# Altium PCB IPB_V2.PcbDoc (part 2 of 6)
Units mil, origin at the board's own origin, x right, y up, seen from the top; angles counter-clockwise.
Board outline 14000 x 12000 mil, 6 copper layers (Top, L2 - Plane/Horiz, L3 - Horiz, L4 - Vert, L5 - Plane/Horiz, Bottom), stack 61.468 mil thick; 657 components, 436 nets, 1897 pads, 873 vias.
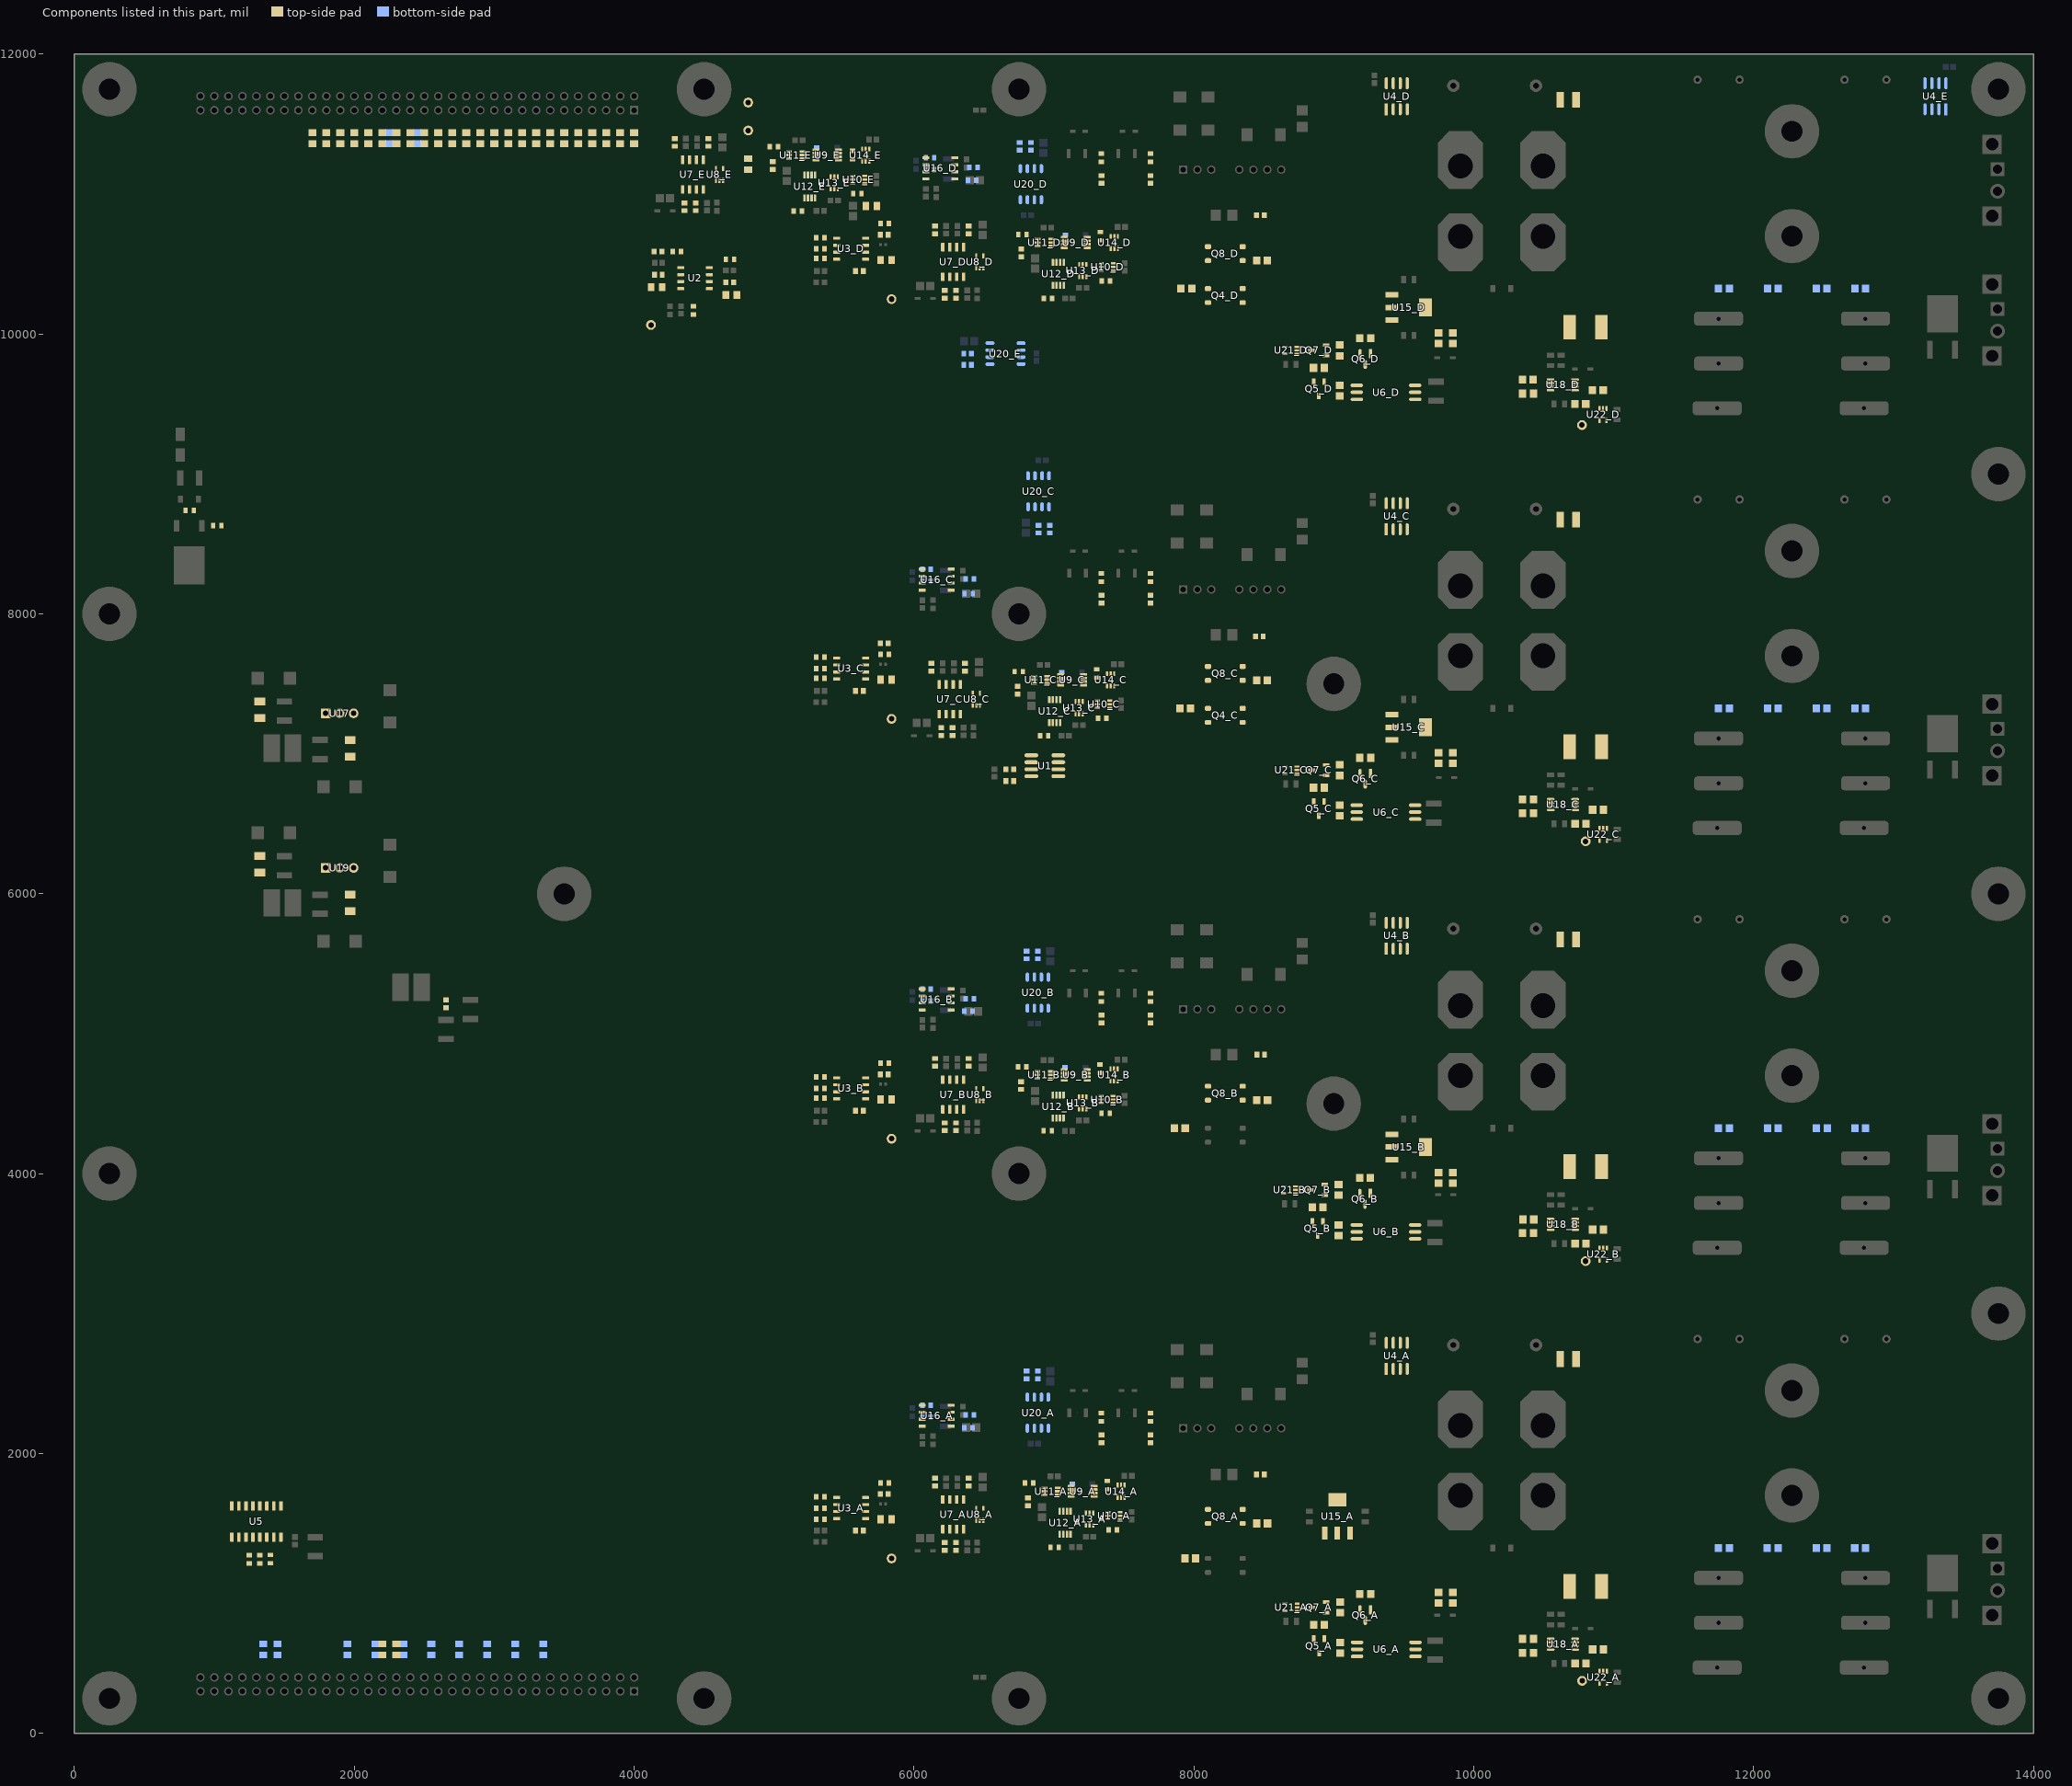
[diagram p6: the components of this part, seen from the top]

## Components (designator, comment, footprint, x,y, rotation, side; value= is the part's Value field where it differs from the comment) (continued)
Q4_C "140357145100" WL-OCPT_SOP4 8225,7275 r0 top (schematic designator Q4)
Q4_D "140357145100" WL-OCPT_SOP4 8225,10275 r0 top (schematic designator Q4)
Q5_A "MMBT3906LT1G" SOT95P237X111-3M 8895,625 r270 top (schematic designator Q5)
Q5_B "MMBT3906LT1G" SOT95P237X111-3M 8884.76,3608.66 r270 top (schematic designator Q5)
Q5_C "MMBT3906LT1G" SOT95P237X111-3M 8893.42,6608.66 r270 top (schematic designator Q5)
Q5_D "MMBT3906LT1G" SOT95P237X111-3M 8893.42,9608.66 r270 top (schematic designator Q5)
Q6_A "BSS138P,215" FP-SOT23-IPC_A 9225,845 r270 top (schematic designator Q6)
Q6_B "BSS138P,215" FP-SOT23-IPC_A 9223.42,3820 r270 top (schematic designator Q6)
Q6_C "BSS138P,215" FP-SOT23-IPC_A 9225,6821.58 r270 top (schematic designator Q6)
Q6_D "BSS138P,215" FP-SOT23-IPC_A 9225,9821.58 r270 top (schematic designator Q6)
Q7_A "MMBT3904LT1G" SOT95P237X111-3M 8895,900 r180 top (schematic designator Q7)
Q7_B "MMBT3904LT1G" SOT95P237X111-3M 8884.76,3883.66 r180 top (schematic designator Q7)
Q7_C "MMBT3904LT1G" SOT95P237X111-3M 8893.42,6883.66 r180 top (schematic designator Q7)
Q7_D "MMBT3904LT1G" SOT95P237X111-3M 8893.42,9883.66 r180 top (schematic designator Q7)
Q8_A "140357145100" WL-OCPT_SOP4 8225,1550 r180 top (schematic designator Q8)
Q8_B "140357145100" WL-OCPT_SOP4 8225,4575 r180 top (schematic designator Q8)
Q8_C "140357145100" WL-OCPT_SOP4 8225,7575 r180 top (schematic designator Q8)
Q8_D "140357145100" WL-OCPT_SOP4 8225,10575 r180 top (schematic designator Q8)
R1 "Resistor 51R1 +/-1% 0603 100 mW" RESC1609X50X30ML08T20 6685,6805 r0 top value=51.1
R2 "Resistor 7K15 +/-1% 0603 100 mW" RESC1609X50X30ML08T20 6685,6890 r0 top value=7.15k
R3 "Resistor 0R +/- 5% 0805 125 mW" RESC2013X60X35ML10T20 3200,11400 r90 top value=0
R4 "Resistor 0R +/- 5% 0805 125 mW" RESC2013X60X35ML10T20 4000,11400 r90 top value=0
R5 "Resistor 0R +/- 5% 0805 125 mW" RESC2013X60X35ML10T20 3100,11400 r90 top value=0
R6 "Resistor 0R +/- 5% 0805 125 mW" RESC2013X60X35ML10T20 3900,11400 r90 top value=0
R7 "Resistor 0R +/- 5% 0805 125 mW" RESC2013X60X35ML10T20 2800,11400 r90 top value=0
R8 "Resistor 0R +/- 5% 0805 125 mW" RESC2013X60X35ML10T20 3800,11400 r90 top value=0
R9 "Resistor 0R +/- 5% 0805 125 mW" RESC2013X60X35ML10T20 2700,11400 r90 top value=0
R10 "Resistor 0R +/- 5% 0805 125 mW" RESC2013X60X35ML10T20 3700,11400 r90 top value=0
R11 "Resistor 0R +/- 5% 0805 125 mW" RESC2013X60X35ML10T20 2400,11400 r90 top value=0
R12 "Resistor 0R +/- 5% 0805 125 mW" RESC2013X60X35ML10T20 3600,11400 r90 top value=0
R13 "Resistor 0R +/- 5% 0805 125 mW" RESC2013X60X35ML10T20 2300,11400 r90 top value=0
R14 "Resistor 0R +/- 5% 0805 125 mW" RESC2013X60X35ML10T20 3500,11400 r90 top value=0
R15 "Resistor 0R +/- 5% 0805 125 mW" RESC2013X60X35ML10T20 2000,11400 r90 top value=0
R16 "Resistor 0R +/- 5% 0805 125 mW" RESC2013X60X35ML10T20 3400,11400 r90 top value=0
R17 "Resistor 0R +/- 5% 0805 125 mW" RESC2013X60X35ML10T20 1900,11400 r90 top value=0
R18 "Resistor 0R +/- 5% 0805 125 mW" RESC2013X60X35ML10T20 3300,11400 r90 top value=0
R19 "Resistor 0R +/- 5% 0805 125 mW" RESC2013X60X35ML10T20 3000,11400 r90 top value=0
R20 "Resistor 0R +/- 5% 0805 125 mW" RESC2013X60X35ML10T20 3350,599.37 r270 bottom value=0
R21 "Resistor 0R +/- 5% 0805 125 mW" RESC2013X60X35ML10T20 2900,11400 r90 top value=0
R22 "Resistor 0R +/- 5% 0805 125 mW" RESC2013X60X35ML10T20 3150,599.37 r270 bottom value=0
R23 "Resistor 0R +/- 5% 0805 125 mW" RESC2013X60X35ML10T20 2600,11400 r90 top value=0
R24 "Resistor 0R +/- 5% 0805 125 mW" RESC2013X60X35ML10T20 2950,599.37 r270 bottom value=0
R25 "Resistor 0R +/- 5% 0805 125 mW" RESC2013X60X35ML10T20 2500,11400 r90 top value=0
R26 "Resistor 0R +/- 5% 0805 125 mW" RESC2013X60X35ML10T20 2750,599.37 r270 bottom value=0
R27 "Resistor 0R +/- 5% 0805 125 mW" RESC2013X60X35ML10T20 2200,11400 r90 top value=0
R28 "Resistor 0R +/- 5% 0805 125 mW" RESC2013X60X35ML10T20 2550,599.37 r270 bottom value=0
R29 "Resistor 0R +/- 5% 0805 125 mW" RESC2013X60X35ML10T20 2100,11400 r90 top value=0
R30 "Resistor 0R +/- 5% 0805 125 mW" RESC2013X60X35ML10T20 2350,599.37 r270 bottom value=0
R31 "Resistor 0R +/- 5% 0805 125 mW" RESC2013X60X35ML10T20 1800,11400 r90 top value=0
R32 "Resistor 0R +/- 5% 0805 125 mW" RESC2013X60X35ML10T20 2150,599.37 r270 bottom value=0
R33 "Resistor 0R +/- 5% 0805 125 mW" RESC2013X60X35ML10T20 2450,11400 r90 bottom value=0
R34 "Resistor 0R +/- 5% 0805 125 mW" RESC2013X60X35ML10T20 1700,11400 r90 top value=0
R35 "Resistor 0R +/- 5% 0805 125 mW" RESC2013X60X35ML10T20 1950,599.37 r270 bottom value=0
R36 "Resistor 0R +/- 5% 0805 125 mW" RESC2013X60X35ML10T20 2250,11400 r90 bottom value=0
R37 "Resistor 0R +/- 5% 0805 125 mW" RESC2013X60X35ML10T20 2300,600 r270 top value=0
R38 "Resistor 0R +/- 5% 0805 125 mW" RESC2013X60X35ML10T20 2200,600 r270 top value=0
R39 "Resistor 0R +/- 5% 0805 125 mW" RESC2013X60X35ML10T20 1450,599.37 r270 bottom value=0
R40 "Resistor 0R +/- 5% 0805 125 mW" RESC2013X60X35ML10T20 1350,599.37 r270 bottom value=0
R41 "Resistor 0R +/- 5% 0805 125 mW" RESC2013X60X35ML10T20 4815,11214.84 r270 top value=0
R42 "Resistor 0R +/- 5% 0805 125 mW" RESC2013X60X35ML10T20 5695,10915 r0 top value=0
R43 "Resistor 8K25 +/-1% 0603 100 mW" RESC1609X50X30ML08T20 4683.19,10370 r0 top value=8.25k
R44 "Resistor 10k +/-1% 0603 100 mW" RESC1608X55X25ML10T15 4425,10170 r90 top value=10k
R45 "Resistor 0R +/- 5% 0805 125 mW" RESC2013X60X35ML10T20 4695,10280 r180 top value=0
R46 "Resistor 45K3 +/-1% 0603 100 mW" RESC1608X55X25ML10T15 4685.16,10535 r180 top value=45.3k
R47 "Resistor 2K49 +/-1% 0603 100 mW" RESC1609X50X30ML08T20 4172.56,10425 r180 top value=2.49k
R48 "Resistor 3K32 +/-1% 0603 100 mW" RESC1609X50X30ML08T20 4170.47,10590 r0 top value=3.32k
R49 "Resistor 0R +/- 5% 0805 125 mW" RESC2013X60X35ML10T20 4160.75,10335 r0 top value=0
R50 "Resistor 10k +/-1% 0603 100 mW" RESC1608X55X25ML10T15 4305,10590 r180 top value=10k
R51_A "Resistor 4K53 +/-1% 0603 100 mW" RESC1609X50X30ML08T20 5610,1450 r0 top value=4.53k (schematic designator R51)
R51_B "Resistor 4K53 +/-1% 0603 100 mW" RESC1609X50X30ML08T20 5610,4450 r0 top value=4.53k (schematic designator R51)
R51_C "Resistor 4K53 +/-1% 0603 100 mW" RESC1609X50X30ML08T20 5610,7450 r0 top value=4.53k (schematic designator R51)
R51_D "Resistor 4K53 +/-1% 0603 100 mW" RESC1609X50X30ML08T20 5610,10450 r0 top value=4.53k (schematic designator R51)
R52_A "Resistor 10k +/-1% 0603 100 mW" RESC1608X55X25ML10T15 5790.16,1790 r0 top value=10k (schematic designator R52)
R52_B "Resistor 10k +/-1% 0603 100 mW" RESC1608X55X25ML10T15 5790.16,4790 r0 top value=10k (schematic designator R52)
R52_C "Resistor 10k +/-1% 0603 100 mW" RESC1608X55X25ML10T15 5790.16,7710 r0 top value=10k (schematic designator R52)
R52_D "Resistor 10k +/-1% 0603 100 mW" RESC1608X55X25ML10T15 5790.16,10790 r0 top value=10k (schematic designator R52)
R53_A "Resistor 0R +/- 5% 0805 125 mW" RESC2013X60X35ML10T20 5800,1530 r180 top value=0 (schematic designator R53)
R53_B "Resistor 0R +/- 5% 0805 125 mW" RESC2013X60X35ML10T20 5800,4530 r180 top value=0 (schematic designator R53)
R53_C "Resistor 0R +/- 5% 0805 125 mW" RESC2013X60X35ML10T20 5800,7530 r180 top value=0 (schematic designator R53)
R53_D "Resistor 0R +/- 5% 0805 125 mW" RESC2013X60X35ML10T20 5800,10530 r180 top value=0 (schematic designator R53)
R54_A "Resistor 8K45 +/-1% 0603 100 mW" RESC1609X50X30ML08T20 5788.19,1710 r180 top value=8.45k (schematic designator R54)
R54_B "Resistor 8K45 +/-1% 0603 100 mW" RESC1609X50X30ML08T20 5788.19,4710 r180 top value=8.45k (schematic designator R54)
R54_C "Resistor 8K45 +/-1% 0603 100 mW" RESC1609X50X30ML08T20 5788.19,7790 r180 top value=8.45k (schematic designator R54)
R54_D "Resistor 8K45 +/-1% 0603 100 mW" RESC1609X50X30ML08T20 5788.19,10710 r180 top value=8.45k (schematic designator R54)
R55_A "Resistor 10k +/-1% 0603 100 mW" RESC1608X55X25ML10T15 5330,1610 r180 top value=10k (schematic designator R55)
R55_B "Resistor 10k +/-1% 0603 100 mW" RESC1608X55X25ML10T15 5330,4610 r180 top value=10k (schematic designator R55)
R55_C "Resistor 10k +/-1% 0603 100 mW" RESC1608X55X25ML10T15 5330,7610 r180 top value=10k (schematic designator R55)
R55_D "Resistor 10k +/-1% 0603 100 mW" RESC1608X55X25ML10T15 5330,10610 r180 top value=10k (schematic designator R55)
R56_A "Resistor 10k +/-1% 0603 100 mW" RESC1608X55X25ML10T15 5330,1690 r0 top value=10k (schematic designator R56)
R56_B "Resistor 10k +/-1% 0603 100 mW" RESC1608X55X25ML10T15 5330,4690 r0 top value=10k (schematic designator R56)
R56_C "Resistor 10k +/-1% 0603 100 mW" RESC1608X55X25ML10T15 5330,7690 r0 top value=10k (schematic designator R56)
R56_D "Resistor 10k +/-1% 0603 100 mW" RESC1608X55X25ML10T15 5330,10690 r0 top value=10k (schematic designator R56)
R57_A "Resistor 10k +/-1% 0603 100 mW" RESC1608X55X25ML10T15 5330,1530 r0 top value=10k (schematic designator R57)
R57_B "Resistor 10k +/-1% 0603 100 mW" RESC1608X55X25ML10T15 5330,4540 r0 top value=10k (schematic designator R57)
R57_C "Resistor 10k +/-1% 0603 100 mW" RESC1608X55X25ML10T15 5330,7540 r0 top value=10k (schematic designator R57)
R57_D "Resistor 10k +/-1% 0603 100 mW" RESC1608X55X25ML10T15 5330,10540 r0 top value=10k (schematic designator R57)
R58 "Resistor 49K9 +/-1% 0603 100 mW" RESC1608X55X25ML10T15 822.8,8740 r180 top value=49.9k
R59 "Resistor 3R9 +/-1% 0603 100 mW" RESC1609X50X30ML08T20 2655,5213.78 r90 top value=3.9
R60 "Resistor 49K9 +/-1% 0603 100 mW" RESC1608X55X25ML10T15 1020,8630 r180 top value=49.9k
R61_A "Resistor 2K80 +/-1% 0603 100 mW" RESC1609X50X30ML08T20 8475,1850 r180 top value=2.8k (schematic designator R61)
R61_B "Resistor 2K80 +/-1% 0603 100 mW" RESC1609X50X30ML08T20 8477.56,4850 r180 top value=2.8k (schematic designator R61)
R61_C "Resistor 2K80 +/-1% 0603 100 mW" RESC1609X50X30ML08T20 8467.56,7840 r180 top value=2.8k (schematic designator R61)
R61_D "Resistor 2K80 +/-1% 0603 100 mW" RESC1609X50X30ML08T20 8475,10850 r180 top value=2.8k (schematic designator R61)
R62_A "RES 0805 4K99 1%" PANASONIC_ERJ6E 10763.39,500 r0 top value=4.99k (schematic designator R62)
R62_B "RES 0805 4K99 1%" PANASONIC_ERJ6E 10763.39,3500.2 r0 top value=4.99k (schematic designator R62)
R62_C "RES 0805 4K99 1%" PANASONIC_ERJ6E 10763.39,6500.2 r0 top value=4.99k (schematic designator R62)
R62_D "RES 0805 4K99 1%" PANASONIC_ERJ6E 10762.36,9500 r0 top value=4.99k (schematic designator R62)
R63_A "RES 0805 768R 1%" PANASONIC_ERJ6E 7975,1250 r0 top value=768 (schematic designator R63)
R63_B "RES 0805 768R 1%" PANASONIC_ERJ6E 7900,4325 r0 top value=768 (schematic designator R63)
R63_C "RES 0805 768R 1%" PANASONIC_ERJ6E 7938.39,7325 r0 top value=768 (schematic designator R63)
R63_D "RES 0805 768R 1%" PANASONIC_ERJ6E 7946.61,10325 r0 top value=768 (schematic designator R63)
R64_A "Resistor 348R +/-1% 0603 100 mW" RESC1609X50X30ML08T20 7340,2105 r90 top value=348 (schematic designator R64)
R64_B "Resistor 348R +/-1% 0603 100 mW" RESC1609X50X30ML08T20 7690,2105 r90 top value=348 (schematic designator R64)
R64_C "Resistor 348R +/-1% 0603 100 mW" RESC1609X50X30ML08T20 7340,5105 r90 top value=348 (schematic designator R64)
R64_D "Resistor 348R +/-1% 0603 100 mW" RESC1609X50X30ML08T20 7690,5105 r90 top value=348 (schematic designator R64)
R64_E "Resistor 348R +/-1% 0603 100 mW" RESC1609X50X30ML08T20 7340,8105 r90 top value=348 (schematic designator R64)
R64_F "Resistor 348R +/-1% 0603 100 mW" RESC1609X50X30ML08T20 7690,8105 r90 top value=348 (schematic designator R64)
R64_G "Resistor 348R +/-1% 0603 100 mW" RESC1609X50X30ML08T20 7340,11105 r90 top value=348 (schematic designator R64)
R64_H "Resistor 348R +/-1% 0603 100 mW" RESC1609X50X30ML08T20 7690,11105 r90 top value=348 (schematic designator R64)
R65_A "Resistor 10k +/-1% 0603 100 mW" RESC1608X55X25ML10T15 7340,2260 r270 top value=10k (schematic designator R65)
R65_B "Resistor 10k +/-1% 0603 100 mW" RESC1608X55X25ML10T15 7690,2260 r270 top value=10k (schematic designator R65)
R65_C "Resistor 10k +/-1% 0603 100 mW" RESC1608X55X25ML10T15 7340,5260 r270 top value=10k (schematic designator R65)
R65_D "Resistor 10k +/-1% 0603 100 mW" RESC1608X55X25ML10T15 7690,5260 r270 top value=10k (schematic designator R65)
R65_E "Resistor 10k +/-1% 0603 100 mW" RESC1608X55X25ML10T15 7340,8260 r270 top value=10k (schematic designator R65)
R65_F "Resistor 10k +/-1% 0603 100 mW" RESC1608X55X25ML10T15 7690,8260 r270 top value=10k (schematic designator R65)
R65_G "Resistor 10k +/-1% 0603 100 mW" RESC1608X55X25ML10T15 7340,11260 r270 top value=10k (schematic designator R65)
R65_H "Resistor 10k +/-1% 0603 100 mW" RESC1608X55X25ML10T15 7690,11260 r270 top value=10k (schematic designator R65)
R66_A "Resistor 1K65 +/-1% 0603 100 mW" RESC1609X50X30ML08T20 6390,1795 r270 top value=1.65k (schematic designator R66)
R66_B "Resistor 1K65 +/-1% 0603 100 mW" RESC1609X50X30ML08T20 6390,4795 r270 top value=1.65k (schematic designator R66)
R66_C "Resistor 1K65 +/-1% 0603 100 mW" RESC1609X50X30ML08T20 6365,7620 r270 top value=1.65k (schematic designator R66)
R66_D "Resistor 1K65 +/-1% 0603 100 mW" RESC1609X50X30ML08T20 6390,10745 r270 top value=1.65k (schematic designator R66)
R66_E "Resistor 1K65 +/-1% 0603 100 mW" RESC1609X50X30ML08T20 4530,11370 r270 top value=1.65k (schematic designator R66)
R67_A "Resistor 499R +/-1% 0603 100 mW" RESC1609X50X30ML08T20 6300,1335 r270 top value=499 (schematic designator R67)
R67_B "Resistor 499R +/-1% 0603 100 mW" RESC1609X50X30ML08T20 6300,4335 r270 top value=499 (schematic designator R67)
R67_C "Resistor 499R +/-1% 0603 100 mW" RESC1609X50X30ML08T20 6275,7160 r270 top value=499 (schematic designator R67)
R67_D "Resistor 499R +/-1% 0603 100 mW" RESC1609X50X30ML08T20 6300,10285 r270 top value=499 (schematic designator R67)
R67_E "Resistor 499R +/-1% 0603 100 mW" RESC1609X50X30ML08T20 4440,10910 r270 top value=499 (schematic designator R67)
R68_A "Resistor 332K +/-1% 0603 100 mW" RESC1609X50X30ML08T20 6220,1335 r90 top value=332k (schematic designator R68)
R68_B "Resistor 332K +/-1% 0603 100 mW" RESC1609X50X30ML08T20 6220,4335 r90 top value=332k (schematic designator R68)
R68_C "Resistor 332K +/-1% 0603 100 mW" RESC1609X50X30ML08T20 6195,7160 r90 top value=332k (schematic designator R68)
R68_D "Resistor 332K +/-1% 0603 100 mW" RESC1609X50X30ML08T20 6220,10285 r90 top value=332k (schematic designator R68)
R68_E "Resistor 332K +/-1% 0603 100 mW" RESC1609X50X30ML08T20 4360,10910 r90 top value=332k (schematic designator R68)
R69_A "Resistor 1K65 +/-1% 0603 100 mW" RESC1609X50X30ML08T20 6150,1795 r270 top value=1.65k (schematic designator R69)
R69_B "Resistor 1K65 +/-1% 0603 100 mW" RESC1609X50X30ML08T20 6150,4795 r270 top value=1.65k (schematic designator R69)
R69_C "Resistor 1K65 +/-1% 0603 100 mW" RESC1609X50X30ML08T20 6125,7620 r270 top value=1.65k (schematic designator R69)
R69_D "Resistor 1K65 +/-1% 0603 100 mW" RESC1609X50X30ML08T20 6150,10745 r270 top value=1.65k (schematic designator R69)
R69_E "Resistor 1K65 +/-1% 0603 100 mW" RESC1609X50X30ML08T20 4290,11370 r270 top value=1.65k (schematic designator R69)
R70_A "Resistor 49K9 +/-1% 0603 100 mW" RESC1608X55X25ML10T15 7130,1755 r270 bottom value=49.9k (schematic designator R70)
R70_B "Resistor 49K9 +/-1% 0603 100 mW" RESC1608X55X25ML10T15 7080,4730 r270 bottom value=49.9k (schematic designator R70)
R70_C "Resistor 49K9 +/-1% 0603 100 mW" RESC1608X55X25ML10T15 7055,7555 r270 bottom value=49.9k (schematic designator R70)
R70_D "Resistor 49K9 +/-1% 0603 100 mW" RESC1608X55X25ML10T15 7081.54,10680 r270 bottom value=49.9k (schematic designator R70)
R70_E "Resistor 49K9 +/-1% 0603 100 mW" RESC1608X55X25ML10T15 5305,11305 r270 bottom value=49.9k (schematic designator R70)
R71_A "Resistor 49K9 +/-1% 0603 100 mW" RESC1608X55X25ML10T15 6823,1788 r0 top value=49.9k (schematic designator R71)
R71_B "Resistor 49K9 +/-1% 0603 100 mW" RESC1608X55X25ML10T15 6773,4763 r0 top value=49.9k (schematic designator R71)
R71_C "Resistor 49K9 +/-1% 0603 100 mW" RESC1608X55X25ML10T15 6748,7588 r0 top value=49.9k (schematic designator R71)
R71_D "Resistor 49K9 +/-1% 0603 100 mW" RESC1608X55X25ML10T15 6774.53,10713 r0 top value=49.9k (schematic designator R71)
R71_E "Resistor 49K9 +/-1% 0603 100 mW" RESC1608X55X25ML10T15 4998,11338 r0 top value=49.9k (schematic designator R71)
R72_A "Resistor 332K +/-1% 0603 100 mW" RESC1609X50X30ML08T20 6815,1655 r90 top value=332k (schematic designator R72)
R72_B "Resistor 332K +/-1% 0603 100 mW" RESC1609X50X30ML08T20 6765,4630 r90 top value=332k (schematic designator R72)
R72_C "Resistor 332K +/-1% 0603 100 mW" RESC1609X50X30ML08T20 6740,7455 r90 top value=332k (schematic designator R72)
R72_D "Resistor 332K +/-1% 0603 100 mW" RESC1609X50X30ML08T20 6766.54,10580 r90 top value=332k (schematic designator R72)
R72_E "Resistor 332K +/-1% 0603 100 mW" RESC1609X50X30ML08T20 4990,11205 r90 top value=332k (schematic designator R72)
R73_A "Resistor 49K9 +/-1% 0603 100 mW" RESC1608X55X25ML10T15 7420,1455 r180 top value=49.9k (schematic designator R73)
R73_B "Resistor 49K9 +/-1% 0603 100 mW" RESC1608X55X25ML10T15 7370,4430 r180 top value=49.9k (schematic designator R73)
R73_C "Resistor 49K9 +/-1% 0603 100 mW" RESC1608X55X25ML10T15 7345,7255 r180 top value=49.9k (schematic designator R73)
R73_D "Resistor 49K9 +/-1% 0603 100 mW" RESC1608X55X25ML10T15 7371.53,10380 r180 top value=49.9k (schematic designator R73)
R73_E "Resistor 49K9 +/-1% 0603 100 mW" RESC1608X55X25ML10T15 5595,11005 r180 top value=49.9k (schematic designator R73)
R74_A "Resistor 49K9 +/-1% 0603 100 mW" RESC1608X55X25ML10T15 7380,1775 r270 top value=49.9k (schematic designator R74)
R74_B "Resistor 49K9 +/-1% 0603 100 mW" RESC1608X55X25ML10T15 7330,4750 r270 top value=49.9k (schematic designator R74)
R74_C "Resistor 49K9 +/-1% 0603 100 mW" RESC1608X55X25ML10T15 7305,7575 r270 top value=49.9k (schematic designator R74)
R74_D "Resistor 49K9 +/-1% 0603 100 mW" RESC1608X55X25ML10T15 7331.54,10700 r270 top value=49.9k (schematic designator R74)
R74_E "Resistor 49K9 +/-1% 0603 100 mW" RESC1608X55X25ML10T15 5560,11280 r270 top value=49.9k (schematic designator R74)
R75_A "Resistor 49K9 +/-1% 0603 100 mW" RESC1608X55X25ML10T15 7005,1330 r0 top value=49.9k (schematic designator R75)
R75_B "Resistor 49K9 +/-1% 0603 100 mW" RESC1608X55X25ML10T15 6955,4305 r0 top value=49.9k (schematic designator R75)
R75_C "Resistor 49K9 +/-1% 0603 100 mW" RESC1608X55X25ML10T15 6930,7130 r0 top value=49.9k (schematic designator R75)
R75_D "Resistor 49K9 +/-1% 0603 100 mW" RESC1608X55X25ML10T15 6956.54,10255 r0 top value=49.9k (schematic designator R75)
R75_E "Resistor 49K9 +/-1% 0603 100 mW" RESC1608X55X25ML10T15 5170,10880 r0 top value=49.9k (schematic designator R75)
R76_A "RES 0805 294R 1%" PANASONIC_ERJ6E 9045,611.61 r90 top value=294 (schematic designator R76)
R76_B "RES 0805 294R 1%" PANASONIC_ERJ6E 9034.76,3595.28 r90 top value=294 (schematic designator R76)
R76_C "RES 0805 294R 1%" PANASONIC_ERJ6E 9043.42,6595.28 r90 top value=294 (schematic designator R76)
R76_D "RES 0805 294R 1%" PANASONIC_ERJ6E 9043.42,9595.28 r90 top value=294 (schematic designator R76)
R77_A "Resistor 953R +/-1% 0603 100 mW" RESC1608X55X25ML10T15 6089.21,2259.28 r180 bottom value=953 (schematic designator R77)
R77_B "Resistor 953R +/-1% 0603 100 mW" RESC1608X55X25ML10T15 6089.21,5234.28 r180 bottom value=953 (schematic designator R77)
R77_C "Resistor 953R +/-1% 0603 100 mW" RESC1608X55X25ML10T15 6089.21,8234.28 r180 bottom value=953 (schematic designator R77)
R77_D "Resistor 953R +/-1% 0603 100 mW" RESC1608X55X25ML10T15 6114.21,11174.28 r180 bottom value=953 (schematic designator R77)
R78_A "Resistor 1K50+/-1% 0603 100 mW" RESC1608X55X25ML10T15 6089.21,2345 r180 bottom value=1.50k (schematic designator R78)
R78_B "Resistor 1K50+/-1% 0603 100 mW" RESC1608X55X25ML10T15 6089.21,5320 r180 bottom value=1.50k (schematic designator R78)
R78_C "Resistor 1K50+/-1% 0603 100 mW" RESC1608X55X25ML10T15 6089.21,8320 r180 bottom value=1.50k (schematic designator R78)
R78_D "Resistor 1K50+/-1% 0603 100 mW" RESC1608X55X25ML10T15 6114.21,11260 r180 bottom value=1.50k (schematic designator R78)
R79_A "Resistor 2K43+/-1% 0603 100 mW" RESC1608X55X25ML10T15 6399.21,2275 r0 bottom value=2.43k (schematic designator R79)
R79_B "Resistor 2K43+/-1% 0603 100 mW" RESC1608X55X25ML10T15 6399.21,5250 r0 bottom value=2.43k (schematic designator R79)
R79_C "Resistor 2K43+/-1% 0603 100 mW" RESC1608X55X25ML10T15 6399.21,8250 r0 bottom value=2.43k (schematic designator R79)
R79_D "Resistor 2K43+/-1% 0603 100 mW" RESC1608X55X25ML10T15 6424.21,11190 r0 bottom value=2.43k (schematic designator R79)
R80_A "Resistor 3K48+/-1% 0603 100 mW" RESC1608X55X25ML10T15 6389.53,2185 r180 bottom value=3.48k (schematic designator R80)
R80_B "Resistor 3K48+/-1% 0603 100 mW" RESC1608X55X25ML10T15 6389.53,5160 r180 bottom value=3.48k (schematic designator R80)
R80_C "Resistor 3K48+/-1% 0603 100 mW" RESC1608X55X25ML10T15 6390,8145 r180 bottom value=3.48k (schematic designator R80)
R80_D "Resistor 3K48+/-1% 0603 100 mW" RESC1608X55X25ML10T15 6414.53,11100 r180 bottom value=3.48k (schematic designator R80)
R81 "Res Thick Film 1206 3.3 Ohm 1% 0.5W ±200ppm/°C Molded SMD Punched Carrier T/R" RESC3115X07M 1325,7315 r270 top value=3R3
R82 "Res Thick Film 1206 3.3 Ohm 1% 0.5W ±200ppm/°C Molded SMD Punched Carrier T/R" RESC3115X07M 1970,7040 r90 top value=3R3
R83_A "RES 0805 768R 1%" PANASONIC_ERJ6E 8488.39,1500 r0 top value=768 (schematic designator R83)
R83_B "RES 0805 768R 1%" PANASONIC_ERJ6E 8488.39,4525 r0 top value=768 (schematic designator R83)
R83_C "RES 0805 768R 1%" PANASONIC_ERJ6E 8486.61,7525 r0 top value=768 (schematic designator R83)
R83_D "RES 0805 768R 1%" PANASONIC_ERJ6E 8486.61,10525 r0 top value=768 (schematic designator R83)
R84_A "RES 0805 4K99 1%" PANASONIC_ERJ6E 8895,775 r0 top value=4.99k (schematic designator R84)
R84_B "RES 0805 4K99 1%" PANASONIC_ERJ6E 8884.76,3758.66 r0 top value=4.99k (schematic designator R84)
R84_C "RES 0805 4K99 1%" PANASONIC_ERJ6E 8893.42,6758.66 r0 top value=4.99k (schematic designator R84)
R84_D "RES 0805 4K99 1%" PANASONIC_ERJ6E 8893.42,9758.66 r0 top value=4.99k (schematic designator R84)
R85 "Res Thick Film 1206 3.3 Ohm 1% 0.5W ±200ppm/°C Molded SMD Punched Carrier T/R" RESC3115X07M 1325,6210 r270 top value=3R3
R86 "Res Thick Film 1206 3.3 Ohm 1% 0.5W ±200ppm/°C Molded SMD Punched Carrier T/R" RESC3115X07M 1970,5935 r90 top value=3R3
R87_A "Resistor 100K +/-1% 0603 100 mW" RESC1609X50X30ML08T20 6885.24,2561.46 r270 bottom value=100K (schematic designator R87)
R87_B "Resistor 100K +/-1% 0603 100 mW" RESC1609X50X30ML08T20 6885.24,5563.41 r270 bottom value=100K (schematic designator R87)
R87_C "Resistor 100K +/-1% 0603 100 mW" RESC1609X50X30ML08T20 6890,8606.42 r90 bottom value=100K (schematic designator R87)
R87_D "Resistor 100K +/-1% 0603 100 mW" RESC1609X50X30ML08T20 6835.24,11341.47 r270 bottom value=100K (schematic designator R87)
R87_E "Resistor 100K +/-1% 0603 100 mW" RESC1609X50X30ML08T20 6383.66,9860.36 r0 bottom value=100K (schematic designator R87)
R88_A "Resistor 100K +/-1% 0603 100 mW" RESC1609X50X30ML08T20 6805.24,2561.46 r270 bottom value=100K (schematic designator R88)
R88_B "Resistor 100K +/-1% 0603 100 mW" RESC1609X50X30ML08T20 6805.24,5563.41 r270 bottom value=100K (schematic designator R88)
R88_C "Resistor 100K +/-1% 0603 100 mW" RESC1609X50X30ML08T20 6970,8606.42 r90 bottom value=100K (schematic designator R88)
R88_D "Resistor 100K +/-1% 0603 100 mW" RESC1609X50X30ML08T20 6755.24,11341.47 r270 bottom value=100K (schematic designator R88)
R88_E "Resistor 100K +/-1% 0603 100 mW" RESC1609X50X30ML08T20 6383.66,9780.36 r0 bottom value=100K (schematic designator R88)
R89_A "RES 0805 110R 1%" PANASONIC_ERJ6E 9750,970 r90 top value=110 (schematic designator R89)
R89_B "RES 0805 110R 1%" PANASONIC_ERJ6E 9750,3970 r90 top value=110 (schematic designator R89)
R89_C "RES 0805 110R 1%" PANASONIC_ERJ6E 9750,6970 r90 top value=110 (schematic designator R89)
R89_D "RES 0805 110R 1%" PANASONIC_ERJ6E 9750,9970 r90 top value=110 (schematic designator R89)
R90_A "RES 0805 49K9 1%" PANASONIC_ERJ6E 9225,995 r0 top value=49.9k (schematic designator R90)
R90_B "RES 0805 49K9 1%" PANASONIC_ERJ6E 9223.42,3970 r0 top value=49.9k (schematic designator R90)
R90_C "RES 0805 49K9 1%" PANASONIC_ERJ6E 9225,6971.58 r0 top value=49.9k (schematic designator R90)
R90_D "RES 0805 49K9 1%" PANASONIC_ERJ6E 9225,9971.58 r0 top value=49.9k (schematic designator R90)
R91_A "RES 0805 910R 1%" PANASONIC_ERJ6E 9850,970 r90 top value=910 (schematic designator R91)
R91_B "RES 0805 910R 1%" PANASONIC_ERJ6E 9850,3970 r90 top value=910 (schematic designator R91)
R91_C "RES 0805 910R 1%" PANASONIC_ERJ6E 9850,6970 r90 top value=910 (schematic designator R91)
R91_D "RES 0805 910R 1%" PANASONIC_ERJ6E 9850,9970 r90 top value=910 (schematic designator R91)
R92_A "RES 0805 4K99 1%" PANASONIC_ERJ6E 9045,900 r270 top value=4.99k (schematic designator R92)
R92_B "RES 0805 4K99 1%" PANASONIC_ERJ6E 9034.76,3883.66 r270 top value=4.99k (schematic designator R92)
R92_C "RES 0805 4K99 1%" PANASONIC_ERJ6E 9043.42,6883.66 r270 top value=4.99k (schematic designator R92)
R92_D "RES 0805 4K99 1%" PANASONIC_ERJ6E 9043.42,9883.66 r270 top value=4.99k (schematic designator R92)
R93_A "RES 0805 4K99 1%" PANASONIC_ERJ6E 10888.39,600 r0 top value=4.99k (schematic designator R93)
R93_B "RES 0805 4K99 1%" PANASONIC_ERJ6E 10888.39,3600.2 r0 top value=4.99k (schematic designator R93)
R93_C "RES 0805 4K99 1%" PANASONIC_ERJ6E 10888.39,6600.2 r0 top value=4.99k (schematic designator R93)
R93_D "RES 0805 4K99 1%" PANASONIC_ERJ6E 10887.36,9600 r0 top value=4.99k (schematic designator R93)
R94_A "RES 0805 6K80 1%" PANASONIC_ERJ6E 10388.39,675 r0 top value=6.8k (schematic designator R94)
R94_B "RES 0805 6K80 1%" PANASONIC_ERJ6E 10390.89,3672.7 r0 top value=6.8k (schematic designator R94)
R94_C "RES 0805 6K80 1%" PANASONIC_ERJ6E 10388.39,6675.2 r0 top value=6.8k (schematic designator R94)
R94_D "RES 0805 6K80 1%" PANASONIC_ERJ6E 10387.36,9675 r0 top value=6.8k (schematic designator R94)
R95 "Resistor 0R +/- 5% 0603 100 mW" RESC1608X55X25ML10T15 1250,1244.53 r90 top value=0
R96 "Resistor 0R +/- 5% 0603 100 mW" RESC1608X55X25ML10T15 1325,1244.53 r90 top value=0
R97 "Resistor 0R +/- 5% 0603 100 mW" RESC1608X55X25ML10T15 1400,1245 r90 top value=0
R98_A "RES 0805 3K32 1%" PANASONIC_ERJ6E 10388.39,575 r0 top value=3.32k (schematic designator R98)
R98_B "RES 0805 3K32 1%" PANASONIC_ERJ6E 10388.39,3575.2 r0 top value=3.32k (schematic designator R98)
R98_C "RES 0805 3K32 1%" PANASONIC_ERJ6E 10388.39,6575.2 r0 top value=3.32k (schematic designator R98)
R98_D "RES 0805 3K32 1%" PANASONIC_ERJ6E 10388.39,9575.2 r0 top value=3.32k (schematic designator R98)
R99_A "RES 0805 1M00 1%" PANASONIC_ERJ6E 12761.61,1325 r180 bottom value=1M (schematic designator R99)
R99_B "RES 0805 1M00 1%" PANASONIC_ERJ6E 12763.39,4325 r180 bottom value=1M (schematic designator R99)
R99_C "RES 0805 1M00 1%" PANASONIC_ERJ6E 12763.39,7325 r180 bottom value=1M (schematic designator R99)
R99_D "RES 0805 1M00 1%" PANASONIC_ERJ6E 12763.39,10325 r180 bottom value=1M (schematic designator R99)
R100_A "RES 0805 1M00 1%" PANASONIC_ERJ6E 12486.61,1325 r0 bottom value=1M (schematic designator R100)
R100_B "RES 0805 1M00 1%" PANASONIC_ERJ6E 12488.39,4325 r0 bottom value=1M (schematic designator R100)
R100_C "RES 0805 1M00 1%" PANASONIC_ERJ6E 12486.61,7325 r0 bottom value=1M (schematic designator R100)
R100_D "RES 0805 1M00 1%" PANASONIC_ERJ6E 12486.61,10325 r0 bottom value=1M (schematic designator R100)
R101_A "RES 0805 1M00 1%" PANASONIC_ERJ6E 12136.61,1325 r180 bottom value=1M (schematic designator R101)
R101_B "RES 0805 1M00 1%" PANASONIC_ERJ6E 12138.39,4325 r180 bottom value=1M (schematic designator R101)
R101_C "RES 0805 1M00 1%" PANASONIC_ERJ6E 12138.39,7325 r180 bottom value=1M (schematic designator R101)
R101_D "RES 0805 1M00 1%" PANASONIC_ERJ6E 12138.39,10325 r180 bottom value=1M (schematic designator R101)
R102_A "WSL28165L000FEH" RESC7142X88N 10800,1050 r0 top value=5mR (schematic designator R102)
R102_B "WSL28165L000FEH" RESC7142X88N 10800,4050.2 r0 top value=5mR (schematic designator R102)
R102_C "WSL28165L000FEH" RESC7142X88N 10800,7050.2 r0 top value=5mR (schematic designator R102)
R102_D "WSL28165L000FEH" RESC7142X88N 10798.98,10050 r0 top value=5mR (schematic designator R102)
R103_A "RES 0805 1M00 1%" PANASONIC_ERJ6E 11788.39,1325 r0 bottom value=1M (schematic designator R103)
R103_B "RES 0805 1M00 1%" PANASONIC_ERJ6E 11788.39,4325 r0 bottom value=1M (schematic designator R103)
R103_C "RES 0805 1M00 1%" PANASONIC_ERJ6E 11788.39,7325 r0 bottom value=1M (schematic designator R103)
R103_D "RES 0805 1M00 1%" PANASONIC_ERJ6E 11788.39,10325 r0 bottom value=1M (schematic designator R103)
R104_A "RPC2010JT220R" RESC3126X06M 10675,2675 r0 top value=220R (schematic designator R104)
R104_B "RPC2010JT220R" RESC3126X06M 10675,5675 r0 top value=220R (schematic designator R104)
R104_C "RPC2010JT220R" RESC3126X06M 10675,8675 r0 top value=220R (schematic designator R104)
R104_D "RPC2010JT220R" RESC3126X06M 10675,11675 r0 top value=220R (schematic designator R104)
TP1 "5002" "Keystone 5002" 4815,11455 r0 top
TP2 "5002" "Keystone 5002" 4815,11655 r90 top
TP3 "5002" "Keystone 5002" 4120,10065 r90 top
TP4_A "5002" "Keystone 5002" 5839.37,1250 r90 top (schematic designator TP4)
TP4_B "5002" "Keystone 5002" 5839.37,4250 r90 top (schematic designator TP4)
TP4_C "5002" "Keystone 5002" 5839.37,7250 r90 top (schematic designator TP4)
TP4_D "5002" "Keystone 5002" 5839.37,10250 r90 top (schematic designator TP4)
TP5_A "5001" "Keystone 5001" 10775,375 r90 top (schematic designator TP5)
TP5_B "5001" "Keystone 5001" 10800,3375 r90 top (schematic designator TP5)
TP5_C "5001" "Keystone 5001" 10800,6375 r90 top (schematic designator TP5)
TP5_D "5001" "Keystone 5001" 10773.98,9350 r90 top (schematic designator TP5)
U1 "AD590KRZ-RL" ADI-R-8_M 6935,6915 r0 top
U2 "TLV2452AIDR" D0008A_L 4435,10400 r180 top
U3_A "TLV2452AIDR" D0008A_L 5550,1610 r180 top (schematic designator U3)
U3_B "TLV2452AIDR" D0008A_L 5550,4610 r180 top (schematic designator U3)
U3_C "TLV2452AIDR" D0008A_L 5550,7610 r180 top (schematic designator U3)
U3_D "TLV2452AIDR" D0008A_L 5550,10610 r180 top (schematic designator U3)
U4_A "TMCS1101A4BQDR" FP-D0008A-IPC_B 9450,2698.06 r90 top (schematic designator U4)
U4_B "TMCS1101A4BQDR" FP-D0008A-IPC_B 9450,5700 r90 top (schematic designator U4)
U4_C "TMCS1101A4BQDR" FP-D0008A-IPC_B 9450,8698.06 r90 top (schematic designator U4)
U4_D "TMCS1101A4BQDR" FP-D0008A-IPC_B 9450,11700 r90 top (schematic designator U4)
U4_E "TMCS1101A4BQDR" FP-D0008A-IPC_B 13300,11700 r90 bottom (schematic designator U4)
U5 "SN74HC151QDRQ1" D0016A_M 1300,1513.78 r270 top
U6_A "UCC23511BDWYR" SOIC127P1150X355-6M 9375,600 r0 top (schematic designator U6)
U6_B "UCC23511BDWYR" SOIC127P1150X355-6M 9373.42,3583.66 r0 top (schematic designator U6)
U6_C "UCC23511BDWYR" SOIC127P1150X355-6M 9373.42,6583.66 r0 top (schematic designator U6)
U6_D "UCC23511BDWYR" SOIC127P1150X355-6M 9373.43,9583.66 r0 top (schematic designator U6)
U7_A "TLV3202AIDR" FP-D0008A-MFG 6280,1565 r270 top (schematic designator U7)
U7_B "TLV3202AIDR" FP-D0008A-MFG 6280,4565 r270 top (schematic designator U7)
U7_C "TLV3202AIDR" FP-D0008A-MFG 6255,7390 r270 top (schematic designator U7)
U7_D "TLV3202AIDR" FP-D0008A-MFG 6280,10515 r270 top (schematic designator U7)
U7_E "TLV3202AIDR" FP-D0008A-MFG 4420,11140 r270 top (schematic designator U7)
U8_A "SN74LVC1G17QDCKRQ1" FP-DCK0005A-MFG 6470,1565 r90 top (schematic designator U8)
U8_B "SN74LVC1G17QDCKRQ1" FP-DCK0005A-MFG 6470,4565 r90 top (schematic designator U8)
U8_C "SN74LVC1G17QDCKRQ1" FP-DCK0005A-MFG 6445,7390 r90 top (schematic designator U8)
U8_D "SN74LVC1G17QDCKRQ1" FP-DCK0005A-MFG 6470,10515 r90 top (schematic designator U8)
U8_E "SN74LVC1G17QDCKRQ1" FP-DCK0005A-MFG 4610,11140 r90 top (schematic designator U8)
U9_A "SN74LVC3G14DCTR" DCT0008A_M 7205,1730 r0 top (schematic designator U9)
U9_B "SN74LVC3G14DCTR" DCT0008A_M 7155,4705 r0 top (schematic designator U9)
U9_C "SN74LVC3G14DCTR" DCT0008A_M 7130,7530 r0 top (schematic designator U9)
U9_D "SN74LVC3G14DCTR" DCT0008A_M 7156.54,10655 r0 top (schematic designator U9)
U9_E "SN74LVC3G14DCTR" DCT0008A_M 5380,11280 r0 top (schematic designator U9)
U10_A "SN74LVC1G11MDCKREP" FP-DCK0006A-MFG 7430,1555 r0 top (schematic designator U10)
U10_B "SN74LVC1G11MDCKREP" FP-DCK0006A-MFG 7380,4530 r0 top (schematic designator U10)
U10_C "SN74LVC1G11MDCKREP" FP-DCK0006A-MFG 7355,7355 r0 top (schematic designator U10)
U10_D "SN74LVC1G11MDCKREP" FP-DCK0006A-MFG 7381.54,10480 r0 top (schematic designator U10)
U10_E "SN74LVC1G11MDCKREP" FP-DCK0006A-MFG 5605,11105 r0 top (schematic designator U10)
U11_A "SN74LVC1G175DCKT" DCK0006A_M 6980,1730 r0 top (schematic designator U11)
U11_B "SN74LVC1G175DCKT" DCK0006A_M 6930,4705 r0 top (schematic designator U11)
U11_C "SN74LVC1G175DCKT" DCK0006A_M 6905,7530 r0 top (schematic designator U11)
U11_D "SN74LVC1G175DCKT" DCK0006A_M 6931.54,10655 r0 top (schematic designator U11)
U11_E "SN74LVC1G175DCKT" DCK0006A_M 5155,11280 r0 top (schematic designator U11)
U12_A "SN74LVC3G14DCTR" DCT0008A_M 7080,1505 r270 top (schematic designator U12)
U12_B "SN74LVC3G14DCTR" DCT0008A_M 7030,4480 r270 top (schematic designator U12)
U12_C "SN74LVC3G14DCTR" DCT0008A_M 7005,7305 r270 top (schematic designator U12)
U12_D "SN74LVC3G14DCTR" DCT0008A_M 7031.54,10430 r270 top (schematic designator U12)
U12_E "SN74LVC3G14DCTR" DCT0008A_M 5255,11055 r270 top (schematic designator U12)
U13_A "SN74LVC1G11MDCKREP" FP-DCK0006A-MFG 7255,1530 r270 top (schematic designator U13)
U13_B "SN74LVC1G11MDCKREP" FP-DCK0006A-MFG 7205,4505 r270 top (schematic designator U13)
U13_C "SN74LVC1G11MDCKREP" FP-DCK0006A-MFG 7180,7330 r270 top (schematic designator U13)
U13_D "SN74LVC1G11MDCKREP" FP-DCK0006A-MFG 7206.54,10455 r270 top (schematic designator U13)
U13_E "SN74LVC1G11MDCKREP" FP-DCK0006A-MFG 5430,11080 r270 top (schematic designator U13)
U14_A "SN74LVC1G11MDCKREP" FP-DCK0006A-MFG 7480,1730 r90 top (schematic designator U14)
U14_B "SN74LVC1G11MDCKREP" FP-DCK0006A-MFG 7430,4705 r90 top (schematic designator U14)
U14_C "SN74LVC1G11MDCKREP" FP-DCK0006A-MFG 7405,7530 r90 top (schematic designator U14)
U14_D "SN74LVC1G11MDCKREP" FP-DCK0006A-MFG 7431.54,10655 r90 top (schematic designator U14)
U14_E "SN74LVC1G11MDCKREP" FP-DCK0006A-MFG 5655,11280 r90 top (schematic designator U14)
U15_A "MCP1792-5002H/DB" SOT230P700X180-4M 9025,1550 r90 top (schematic designator U15)
U15_B "MCP1792-5002H/DB" SOT230P700X180-4M 9535.91,4190 r0 top (schematic designator U15)
U15_C "MCP1792-5002H/DB" SOT230P700X180-4M 9535.91,7190 r0 top (schematic designator U15)
U15_D "MCP1792-5002H/DB" SOT230P700X180-4M 9535.91,10190 r0 top (schematic designator U15)
U16_A "TLV2452AIDR" D0008A_L 6162.56,2270 r180 top (schematic designator U16)
U16_B "TLV2452AIDR" D0008A_L 6162.56,5245 r180 top (schematic designator U16)
U16_C "TLV2452AIDR" D0008A_L 6162.56,8245 r180 top (schematic designator U16)
U16_D "TLV2452AIDR" D0008A_L 6187.56,11185 r180 top (schematic designator U16)
U17 "R-785.0-0.5" REPO-R-78XX-3_V 1895,7290 r0 top
U18_A "INA310A1IDGKR" INA310 10637.6,637.2 r0 top (schematic designator U18)
U18_B "INA310A1IDGKR" INA310 10637.6,3637.4 r0 top (schematic designator U18)
U18_C "INA310A1IDGKR" INA310 10637.6,6637.4 r0 top (schematic designator U18)
U18_D "INA310A1IDGKR" INA310 10636.57,9637.2 r0 top (schematic designator U18)
U19 "R-7812-0.5" REPO-R-78XX-3_V 1895,6185 r0 top
U20_A "MAX6175BASA/V+T" SOIC127P600X175-8M 6885.24,2291.47 r90 bottom (schematic designator U20)
U20_B "MAX6175BASA/V+T" SOIC127P600X175-8M 6885.24,5293.41 r90 bottom (schematic designator U20)
U20_C "MAX6175BASA/V+T" SOIC127P600X175-8M 6890,8876.42 r270 bottom (schematic designator U20)
U20_D "MAX6175BASA/V+T" SOIC127P600X175-8M 6835.24,11071.47 r90 bottom (schematic designator U20)
U20_E "MAX6175BASA/V+T" SOIC127P600X175-8M 6653.66,9860.36 r180 bottom (schematic designator U20)
U21_A "SN74LVC1G17QDCKRQ1" FP-DCK0005A-MFG 8695,900 r180 top (schematic designator U21)
U21_B "SN74LVC1G17QDCKRQ1" FP-DCK0005A-MFG 8684.76,3883.66 r180 top (schematic designator U21)
U21_C "SN74LVC1G17QDCKRQ1" FP-DCK0005A-MFG 8693.42,6883.66 r180 top (schematic designator U21)
U21_D "SN74LVC1G17QDCKRQ1" FP-DCK0005A-MFG 8693.42,9883.66 r180 top (schematic designator U21)
U22_A "SN74LVC1G17QDCKRQ1" FP-DCK0005A-MFG 10925,400 r270 top (schematic designator U22)
U22_B "SN74LVC1G17QDCKRQ1" FP-DCK0005A-MFG 10925,3425 r270 top (schematic designator U22)
U22_C "SN74LVC1G17QDCKRQ1" FP-DCK0005A-MFG 10925,6425 r270 top (schematic designator U22)
U22_D "SN74LVC1G17QDCKRQ1" FP-DCK0005A-MFG 10923.98,9425 r270 top (schematic designator U22)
